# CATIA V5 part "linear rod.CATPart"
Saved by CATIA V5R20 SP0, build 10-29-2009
Part number: linear rod
Source: Unknown
Bounding box of the stored display mesh (mm): x -4 to 4, y 0 to 100, z -4 to 4
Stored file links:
  C:\Users\Ikarus\OneDrive - FH JOANNEUM\BAC - Arbeit 1\CAD Modell\CAD-Modell-Step files\linear rod\linear rod.CATPart
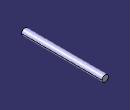
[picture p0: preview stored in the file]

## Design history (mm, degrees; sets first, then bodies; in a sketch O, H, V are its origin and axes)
Body1 (main body)
  Solid1 "Hauptkörper": solid without history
